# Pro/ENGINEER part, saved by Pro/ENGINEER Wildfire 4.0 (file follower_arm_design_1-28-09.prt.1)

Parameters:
  METRIC = "NO"

Other parameters: PITCH, DRILL_DIAMETER, THREAD_DIAMETER, THREADS_PER_INCH, THREAD_DEPTH, THREAD_LENGTH, DRILL_POINT_ANGLE, DRILL_DEPTH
